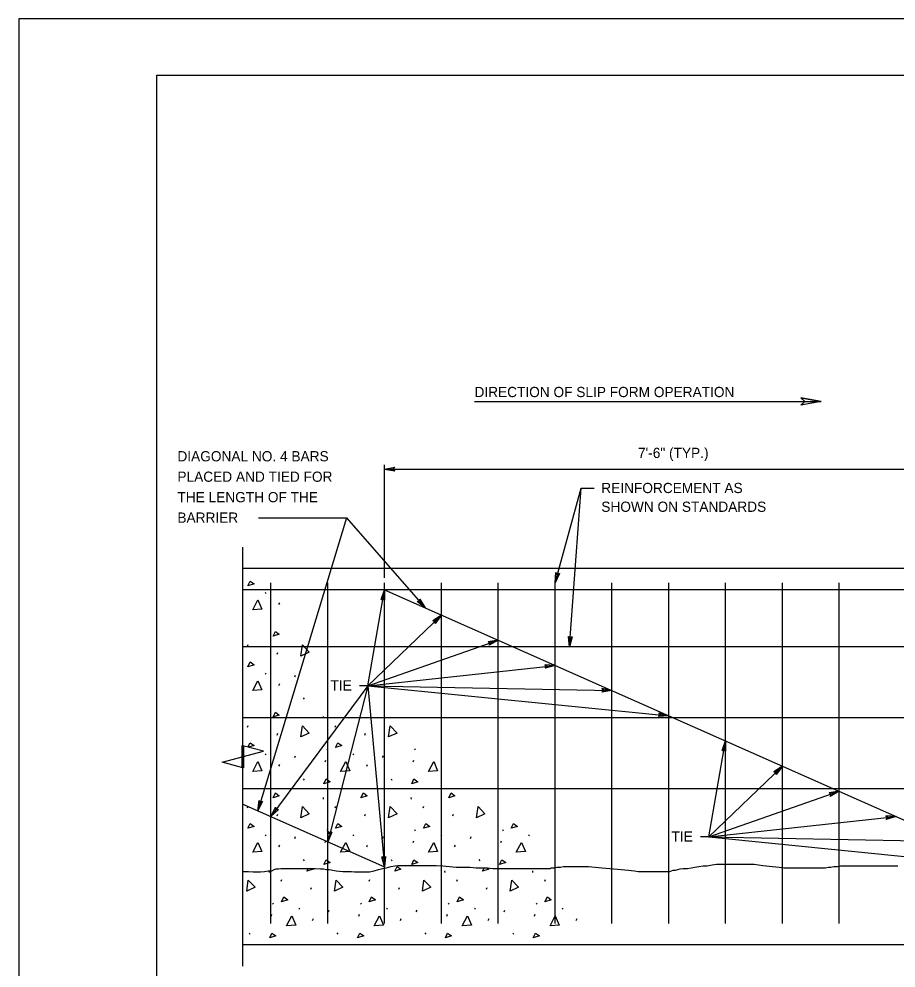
# Model space of a CAD drawing. Extents: x -111.7 to -103.2, y -200 to -189.
# Drawn here: x -111.73 to -106.59, y -194.55 to -188.99 of the extents above; entities that cross this region are included whole.
import ezdxf

# ---------------------------------------------------------------- set-up
doc = ezdxf.new("R2010")
doc.units = 0
for name, color, linetype in [('ANNO-DIMS', 7, 'Continuous'), ('ANNO-TEXT', 7, 'Continuous'), ('BORD-LINE', 7, 'Continuous'), ('DETL-PATT', 7, 'Continuous'), ('Level 10', 7, 'Continuous'), ('Level 12', 7, 'Continuous'), ('SUBS-FOOT_P', 7, 'Continuous'), ('SUPR-PARA_P', 7, 'Continuous'), ('SUPR-RFRC', 7, 'Continuous'), ('USER-CLIP', 7, 'Continuous')]:
    doc.layers.add(name, color=color, linetype=linetype)

msp = doc.modelspace()

# ---------------------------------------------------------------- linework, layer by layer
at = {"layer": 'ANNO-DIMS'}
msp.add_lwpolyline([(-110.4191, -193.3802), (-110.5399, -193.3478), (-110.2984, -193.2831), (-110.4191, -193.2508)], dxfattribs=at)
msp.add_lwpolyline([(-110.4143, -193.3813), (-110.4234, -193.379), (-110.4234, -193.2497), (-110.4143, -193.2521)], close=True, dxfattribs=at)
at = {"layer": 'ANNO-TEXT'}
msp.add_line((-110.4191, -194.5447), (-110.4191, -192.0863), dxfattribs=at)
at = {"layer": 'BORD-LINE'}
msp.add_lwpolyline([(-110.923, -189.3161), (-103.5488, -189.3161), (-103.5488, -199.6692), (-110.923, -199.6692)], close=True, dxfattribs=at)
at = {"layer": 'DETL-PATT'}
for p, q in [((-110.2888, -192.3503), (-110.2837, -192.3568)), ((-110.2077, -192.4225), (-110.2025, -192.4121)), ((-110.3919, -192.6672), (-110.388, -192.6569)), ((-110.218, -192.7136), (-110.2141, -192.7033)), ((-110.2888, -192.8244), (-110.2837, -192.8308)), ((-110.1149, -192.8463), (-110.1098, -192.836)), ((-110.2077, -192.8965), (-110.2025, -192.8862)), ((-110.0647, -192.97), (-110.0595, -192.9777)), ((-109.9487, -193.0795), (-109.9475, -193.0898)), ((-110.3919, -193.1413), (-110.388, -193.131)), ((-110.218, -193.1877), (-110.2141, -193.1774)), ((-109.8766, -193.1413), (-109.8727, -193.131)), ((-109.7027, -193.1877), (-109.6988, -193.1774)), ((-109.9268, -193.2688), (-109.923, -193.2753)), ((-109.4116, -193.2688), (-109.4077, -193.2753)), ((-110.2888, -193.2985), (-110.2837, -193.3049)), ((-110.1149, -193.3204), (-110.1098, -193.31)), ((-109.9359, -193.3448), (-109.932, -193.3345)), ((-109.7735, -193.2985), (-109.7684, -193.3049)), ((-109.5996, -193.3204), (-109.5945, -193.31)), ((-109.4206, -193.3448), (-109.4167, -193.3345)), ((-110.2077, -193.3706), (-110.2025, -193.3603)), ((-109.6924, -193.3706), (-109.6872, -193.3603)), ((-110.0647, -193.444), (-110.0595, -193.4518)), ((-109.5494, -193.444), (-109.5442, -193.4518)), ((-109.9487, -193.5535), (-109.9475, -193.5638)), ((-109.4335, -193.5535), (-109.4322, -193.5638)), ((-110.3919, -193.6154), (-110.388, -193.6051)), ((-109.8766, -193.6154), (-109.8727, -193.6051)), ((-109.3613, -193.6154), (-109.3574, -193.6051)), ((-110.218, -193.6617), (-110.2141, -193.6514)), ((-109.7027, -193.6617), (-109.6988, -193.6514)), ((-109.1874, -193.6617), (-109.1835, -193.6514)), ((-110.2888, -193.7725), (-110.2837, -193.779)), ((-110.1149, -193.7944), (-110.1098, -193.7841)), ((-109.9268, -193.7429), (-109.923, -193.7493)), ((-109.7735, -193.7725), (-109.7684, -193.779)), ((-109.5996, -193.7944), (-109.5945, -193.7841)), ((-109.4116, -193.7429), (-109.4077, -193.7493)), ((-109.2583, -193.7725), (-109.2531, -193.779)), ((-109.0843, -193.7944), (-109.0792, -193.7841)), ((-108.8963, -193.7429), (-108.8924, -193.7493)), ((-108.743, -193.7725), (-108.7378, -193.779)), ((-110.2077, -193.8447), (-110.2025, -193.8344)), ((-109.9359, -193.8189), (-109.932, -193.8086)), ((-109.6924, -193.8447), (-109.6872, -193.8344)), ((-109.4206, -193.8189), (-109.4167, -193.8086)), ((-109.1771, -193.8447), (-109.1719, -193.8344)), ((-108.9053, -193.8189), (-108.9014, -193.8086)), ((-110.0647, -193.9181), (-110.0595, -193.9258)), ((-109.5494, -193.9181), (-109.5442, -193.9258)), ((-109.0341, -193.9181), (-109.0289, -193.9258)), ((-110.2662, -193.9845), (-110.2649, -193.9948)), ((-110.0433, -193.9871), (-110.0349, -193.9701)), ((-109.75, -193.9914), (-109.7496, -193.9948)), ((-109.2356, -193.9845), (-109.2343, -193.9948)), ((-109.0127, -193.9871), (-109.0025, -193.9666)), ((-108.7203, -193.9845), (-108.719, -193.9948)), ((-110.194, -194.0463), (-110.1902, -194.036)), ((-109.6788, -194.0463), (-109.6749, -194.036)), ((-109.1635, -194.0463), (-109.1596, -194.036)), ((-108.6482, -194.0463), (-108.6443, -194.036)), ((-110.0201, -194.0927), (-110.0163, -194.0824)), ((-109.5048, -194.0927), (-109.501, -194.0824)), ((-108.9895, -194.0927), (-108.9857, -194.0824)), ((-110.2443, -194.1739), (-110.2404, -194.1803)), ((-109.729, -194.1739), (-109.7251, -194.1803)), ((-109.2137, -194.1739), (-109.2098, -194.1803)), ((-108.6984, -194.1739), (-108.6945, -194.1803)), ((-110.2533, -194.2499), (-110.2494, -194.2396)), ((-110.091, -194.2035), (-110.0858, -194.2099)), ((-109.9171, -194.2254), (-109.9119, -194.2151)), ((-109.738, -194.2499), (-109.7341, -194.2396)), ((-109.5757, -194.2035), (-109.5705, -194.2099)), ((-109.4018, -194.2254), (-109.3966, -194.2151)), ((-109.2227, -194.2499), (-109.2189, -194.2396)), ((-109.0604, -194.2035), (-109.0552, -194.2099)), ((-108.8865, -194.2254), (-108.8813, -194.2151)), ((-108.7074, -194.2499), (-108.7036, -194.2396)), ((-108.5451, -194.2035), (-108.54, -194.2099)), ((-110.0098, -194.2756), (-110.0047, -194.2653)), ((-109.4945, -194.2756), (-109.4894, -194.2653)), ((-108.9792, -194.2756), (-108.9741, -194.2653)), ((-108.4639, -194.2756), (-108.4588, -194.2653)), ((-110.3821, -194.3491), (-110.377, -194.3568)), ((-109.8668, -194.3491), (-109.8617, -194.3568)), ((-109.3515, -194.3491), (-109.3464, -194.3568)), ((-108.8362, -194.3491), (-108.8311, -194.3568))]:
    msp.add_line(p, q, dxfattribs=at)
for points in [[(-110.3906, -192.313), (-110.3764, -192.2846), (-110.3533, -192.3014), (-110.3906, -192.313)], [(-110.361, -192.4534), (-110.3301, -192.3954), (-110.3069, -192.4495), (-110.361, -192.4534)], [(-110.2412, -192.608), (-110.227, -192.5796), (-110.2051, -192.5964), (-110.2412, -192.608)], [(-110.0789, -192.7252), (-110.0698, -192.6595), (-110.0299, -192.702), (-110.0789, -192.7252)], [(-110.3906, -192.787), (-110.3764, -192.7587), (-110.3533, -192.7754), (-110.3906, -192.787)], [(-110.361, -192.9274), (-110.3301, -192.8695), (-110.3069, -192.9236), (-110.361, -192.9274)], [(-110.2412, -193.082), (-110.227, -193.0537), (-110.2051, -193.0704), (-110.2412, -193.082)], [(-110.0789, -193.1993), (-110.0698, -193.1336), (-110.0299, -193.1761), (-110.0789, -193.1993)], [(-109.5636, -193.1993), (-109.5545, -193.1336), (-109.5146, -193.1761), (-109.5636, -193.1993)], [(-110.3894, -193.2587), (-110.3764, -193.2328), (-110.3533, -193.2495), (-110.386, -193.2597)], [(-109.8753, -193.2611), (-109.8611, -193.2328), (-109.838, -193.2495), (-109.8753, -193.2611)], [(-110.361, -193.4015), (-110.3301, -193.3435), (-110.3069, -193.3976), (-110.361, -193.4015)], [(-109.8457, -193.4015), (-109.8148, -193.3435), (-109.7916, -193.3976), (-109.8457, -193.4015)], [(-109.3304, -193.4015), (-109.2995, -193.3435), (-109.2763, -193.3976), (-109.3304, -193.4015)], [(-109.9436, -193.4737), (-109.9307, -193.4453), (-109.9075, -193.4621), (-109.9436, -193.4737)], [(-109.4283, -193.4737), (-109.4154, -193.4453), (-109.3922, -193.4621), (-109.4283, -193.4737)], [(-110.2412, -193.5561), (-110.227, -193.5278), (-110.2051, -193.5445), (-110.2412, -193.5561)], [(-109.7259, -193.5561), (-109.7117, -193.5278), (-109.6898, -193.5445), (-109.7259, -193.5561)], [(-109.2106, -193.5561), (-109.1964, -193.5278), (-109.1745, -193.5445), (-109.2106, -193.5561)], [(-110.0789, -193.6733), (-110.0698, -193.6076), (-110.0299, -193.6501), (-110.0789, -193.6733)], [(-109.5636, -193.6733), (-109.5545, -193.6076), (-109.5146, -193.6501), (-109.5636, -193.6733)], [(-109.0483, -193.6733), (-109.0393, -193.6076), (-108.9993, -193.6501), (-109.0483, -193.6733)], [(-110.3906, -193.7352), (-110.3764, -193.7068), (-110.3533, -193.7236), (-110.3906, -193.7352)], [(-109.8753, -193.7352), (-109.8611, -193.7068), (-109.838, -193.7236), (-109.8753, -193.7352)], [(-109.36, -193.7352), (-109.3459, -193.7068), (-109.3227, -193.7236), (-109.36, -193.7352)], [(-108.8447, -193.7352), (-108.8306, -193.7068), (-108.8074, -193.7236), (-108.8447, -193.7352)], [(-110.361, -193.8756), (-110.3301, -193.8176), (-110.3069, -193.8717), (-110.361, -193.8756)], [(-109.8457, -193.8756), (-109.8148, -193.8176), (-109.7916, -193.8717), (-109.8457, -193.8756)], [(-109.3304, -193.8756), (-109.2995, -193.8176), (-109.2763, -193.8717), (-109.3304, -193.8756)], [(-108.8151, -193.8756), (-108.7842, -193.8176), (-108.761, -193.8717), (-108.8151, -193.8756)], [(-109.9436, -193.9477), (-109.9307, -193.9194), (-109.9075, -193.9361), (-109.9436, -193.9477)], [(-109.528, -193.9871), (-109.5139, -193.9587), (-109.492, -193.9755), (-109.528, -193.9871)], [(-109.4283, -193.9477), (-109.4154, -193.9194), (-109.3922, -193.9361), (-109.4283, -193.9477)], [(-108.913, -193.9477), (-108.9001, -193.9194), (-108.8769, -193.9361), (-108.913, -193.9477)], [(-110.0142, -193.9701), (-110.0073, -193.9755), (-110.0433, -193.9871)], [(-108.9883, -193.9666), (-108.9767, -193.9755), (-109.0127, -193.9871)], [(-110.3963, -194.1043), (-110.3873, -194.0386), (-110.3473, -194.0811), (-110.3963, -194.1043)], [(-109.881, -194.1043), (-109.872, -194.0386), (-109.8321, -194.0811), (-109.881, -194.1043)], [(-109.3657, -194.1043), (-109.3567, -194.0386), (-109.3168, -194.0811), (-109.3657, -194.1043)], [(-108.8504, -194.1043), (-108.8414, -194.0386), (-108.8015, -194.0811), (-108.8504, -194.1043)], [(-110.1928, -194.1661), (-110.1786, -194.1378), (-110.1554, -194.1545), (-110.1928, -194.1661)], [(-109.6775, -194.1661), (-109.6633, -194.1378), (-109.6401, -194.1545), (-109.6775, -194.1661)], [(-109.1622, -194.1661), (-109.148, -194.1378), (-109.1248, -194.1545), (-109.1622, -194.1661)], [(-108.6469, -194.1661), (-108.6327, -194.1378), (-108.6095, -194.1545), (-108.6469, -194.1661)], [(-110.1631, -194.3065), (-110.1322, -194.2486), (-110.109, -194.3027), (-110.1631, -194.3065)], [(-109.6478, -194.3065), (-109.6169, -194.2486), (-109.5937, -194.3027), (-109.6478, -194.3065)], [(-109.1325, -194.3065), (-109.1016, -194.2486), (-109.0784, -194.3027), (-109.1325, -194.3065)], [(-108.6172, -194.3065), (-108.5863, -194.2486), (-108.5631, -194.3027), (-108.6172, -194.3065)], [(-110.261, -194.3787), (-110.2482, -194.3503), (-110.225, -194.3671), (-110.261, -194.3787)], [(-109.7457, -194.3787), (-109.7329, -194.3503), (-109.7097, -194.3671), (-109.7457, -194.3787)], [(-109.2304, -194.3787), (-109.2176, -194.3503), (-109.1944, -194.3671), (-109.2304, -194.3787)], [(-108.7152, -194.3787), (-108.7023, -194.3503), (-108.6791, -194.3671), (-108.7152, -194.3787)]]:
    msp.add_lwpolyline(points, dxfattribs=at)
at = {"layer": 'Level 10'}
for p, q in [((-109.0603, -191.2304), (-107.0263, -191.2304)), ((-107.0263, -191.2304), (-107.1456, -191.2094)), ((-107.1456, -191.2094), (-107.1229, -191.2304)), ((-107.0263, -191.2304), (-107.1456, -191.2514)), ((-107.1229, -191.2304), (-107.1456, -191.2514)), ((-109.5877, -192.2652), (-109.5877, -191.602)), ((-109.5877, -191.627), (-109.5282, -191.6165)), ((-109.5394, -191.627), (-109.5282, -191.6165)), ((-109.5877, -191.627), (-105.9211, -191.627)), ((-109.5877, -191.627), (-109.5282, -191.6375)), ((-109.5282, -191.6375), (-109.5394, -191.627)), ((-108.5877, -192.2947), (-108.435, -191.7383)), ((-108.5029, -192.6697), (-108.435, -191.7383)), ((-108.435, -191.7383), (-108.3581, -191.7383)), ((-109.8116, -191.9126), (-110.3311, -193.6319)), ((-110.3261, -191.9126), (-109.8116, -191.9126)), ((-109.8116, -191.9126), (-109.3501, -192.4416)), ((-108.5877, -192.2947), (-108.5822, -192.2344)), ((-108.5749, -192.248), (-108.5822, -192.2344)), ((-108.5877, -192.2947), (-108.5619, -192.2401)), ((-108.5619, -192.2401), (-108.5749, -192.248)), ((-109.6859, -192.8994), (-109.5877, -192.3363)), ((-109.5877, -192.3363), (-109.6082, -192.3932)), ((-109.5877, -192.3363), (-109.5876, -192.3967)), ((-109.6082, -192.3932), (-109.596, -192.3839)), ((-109.596, -192.3839), (-109.5876, -192.3967)), ((-109.3501, -192.4416), (-109.3971, -192.4035)), ((-109.3818, -192.4053), (-109.3971, -192.4035)), ((-109.3812, -192.3899), (-109.3818, -192.4053)), ((-109.3501, -192.4416), (-109.3812, -192.3899)), ((-109.6859, -192.8994), (-109.2544, -192.4841)), ((-109.2544, -192.4841), (-109.3045, -192.5178)), ((-109.2544, -192.4841), (-109.2899, -192.5329)), ((-109.3045, -192.5178), (-109.2892, -192.5175)), ((-109.2892, -192.5175), (-109.2899, -192.5329)), ((-108.5029, -192.6697), (-108.5092, -192.6094)), ((-108.4993, -192.6214), (-108.5092, -192.6094)), ((-108.5029, -192.6697), (-108.4881, -192.6109)), ((-108.4881, -192.6109), (-108.4993, -192.6214)), ((-109.6859, -192.8994), (-108.921, -192.6318)), ((-108.921, -192.6318), (-108.9807, -192.6416)), ((-108.9807, -192.6416), (-108.9666, -192.6477)), ((-108.921, -192.6318), (-108.9737, -192.6614)), ((-108.9666, -192.6477), (-108.9737, -192.6614)), ((-109.6859, -192.8994), (-108.5877, -192.7795)), ((-108.5877, -192.7795), (-108.648, -192.7756)), ((-108.648, -192.7756), (-108.6357, -192.7847)), ((-108.5877, -192.7795), (-108.6457, -192.7964)), ((-108.6357, -192.7847), (-108.6457, -192.7964)), ((-109.6859, -192.8994), (-110.2544, -193.6659)), ((-109.6859, -192.8994), (-109.921, -193.8136)), ((-109.6859, -192.8994), (-109.7343, -192.8994)), ((-109.6859, -192.8994), (-108.2544, -192.9272)), ((-109.6859, -192.8994), (-107.921, -193.075)), ((-109.6859, -192.8994), (-109.5877, -193.9613)), ((-108.3027, -192.9263), (-108.3141, -192.9366)), ((-108.2544, -192.9272), (-108.3141, -192.9366)), ((-108.2544, -192.9272), (-108.3137, -192.9157)), ((-108.3137, -192.9157), (-108.3027, -192.9263)), ((-107.9691, -193.0702), (-107.9813, -193.0796)), ((-107.921, -193.075), (-107.9792, -193.0587)), ((-107.9792, -193.0587), (-107.9691, -193.0702)), ((-107.921, -193.075), (-107.9813, -193.0796)), ((-107.6859, -193.7857), (-107.5877, -193.2227)), ((-107.5877, -193.2227), (-107.6082, -193.2795)), ((-107.5877, -193.2227), (-107.5876, -193.2831)), ((-107.6082, -193.2795), (-107.596, -193.2703)), ((-107.596, -193.2703), (-107.5876, -193.2831)), ((-107.6859, -193.7857), (-107.2544, -193.3704)), ((-107.2544, -193.3704), (-107.3045, -193.4042)), ((-107.3045, -193.4042), (-107.2892, -193.4039)), ((-107.2544, -193.3704), (-107.2899, -193.4193)), ((-107.2892, -193.4039), (-107.2899, -193.4193)), ((-110.3311, -193.6319), (-110.324, -193.5719)), ((-110.3172, -193.5856), (-110.324, -193.5719)), ((-107.6859, -193.7857), (-106.9211, -193.5181)), ((-106.9211, -193.5181), (-106.9807, -193.528)), ((-106.9807, -193.528), (-106.9666, -193.5341)), ((-106.9211, -193.5181), (-106.9737, -193.5477)), ((-106.9666, -193.5341), (-106.9737, -193.5477)), ((-110.3311, -193.6319), (-110.3039, -193.5779)), ((-110.3039, -193.5779), (-110.3172, -193.5856)), ((-110.2544, -193.6659), (-110.2274, -193.6118)), ((-110.2544, -193.6659), (-110.2105, -193.6243)), ((-110.2256, -193.6271), (-110.2274, -193.6118)), ((-110.2105, -193.6243), (-110.2256, -193.6271)), ((-107.6859, -193.7857), (-106.5877, -193.6659)), ((-106.5877, -193.6659), (-106.648, -193.662)), ((-106.648, -193.662), (-106.6357, -193.6711)), ((-106.5877, -193.6659), (-106.6457, -193.6828)), ((-106.6357, -193.6711), (-106.6457, -193.6828)), ((-109.921, -193.8136), (-109.9164, -193.7534)), ((-109.921, -193.8136), (-109.8961, -193.7586)), ((-109.909, -193.7668), (-109.9164, -193.7534)), ((-109.8961, -193.7586), (-109.909, -193.7668)), ((-107.6859, -193.7857), (-107.7343, -193.7857)), ((-107.6859, -193.7857), (-106.2544, -193.8136)), ((-107.6859, -193.7857), (-105.9211, -193.9613)), ((-109.5877, -193.9613), (-109.6037, -193.9031)), ((-109.5922, -193.9133), (-109.6037, -193.9031)), ((-109.5828, -193.9011), (-109.5922, -193.9133)), ((-109.5877, -193.9613), (-109.5828, -193.9011))]:
    msp.add_line(p, q, dxfattribs=at)
for points in [[(-107.1456, -191.2094), (-107.0263, -191.2304), (-107.1456, -191.2514), (-107.1229, -191.2304)], [(-109.5282, -191.6375), (-109.5877, -191.627), (-109.5282, -191.6165), (-109.5394, -191.627)], [(-108.5619, -192.2401), (-108.5877, -192.2947), (-108.5822, -192.2344), (-108.5749, -192.248)], [(-109.6082, -192.3932), (-109.5877, -192.3363), (-109.5876, -192.3967), (-109.596, -192.3839)], [(-109.3812, -192.3899), (-109.3501, -192.4416), (-109.3971, -192.4035), (-109.3818, -192.4053)], [(-109.3045, -192.5178), (-109.2544, -192.4841), (-109.2899, -192.5329), (-109.2892, -192.5175)], [(-108.4881, -192.6109), (-108.5029, -192.6697), (-108.5092, -192.6094), (-108.4993, -192.6214)], [(-108.9807, -192.6416), (-108.921, -192.6318), (-108.9737, -192.6614), (-108.9666, -192.6477)], [(-108.648, -192.7756), (-108.5877, -192.7795), (-108.6457, -192.7964), (-108.6357, -192.7847)], [(-108.3137, -192.9157), (-108.2544, -192.9272), (-108.3141, -192.9366), (-108.3027, -192.9263)], [(-107.9792, -193.0587), (-107.921, -193.075), (-107.9813, -193.0796), (-107.9691, -193.0702)], [(-107.6082, -193.2795), (-107.5877, -193.2227), (-107.5876, -193.2831), (-107.596, -193.2703)], [(-107.3045, -193.4042), (-107.2544, -193.3704), (-107.2899, -193.4193), (-107.2892, -193.4039)], [(-110.3039, -193.5779), (-110.3311, -193.6319), (-110.324, -193.5719), (-110.3172, -193.5856)], [(-106.9807, -193.528), (-106.9211, -193.5181), (-106.9737, -193.5477), (-106.9666, -193.5341)], [(-110.2105, -193.6243), (-110.2544, -193.6659), (-110.2274, -193.6118), (-110.2256, -193.6271)], [(-106.648, -193.662), (-106.5877, -193.6659), (-106.6457, -193.6828), (-106.6357, -193.6711)], [(-109.8961, -193.7586), (-109.921, -193.8136), (-109.9164, -193.7534), (-109.909, -193.7668)], [(-109.5828, -193.9011), (-109.5877, -193.9613), (-109.6037, -193.9031), (-109.5922, -193.9133)]]:
    msp.add_lwpolyline(points, close=True, dxfattribs=at)
at = {"layer": 'SUBS-FOOT_P'}
msp.add_line((-105.8377, -194.4197), (-110.4191, -194.4197), dxfattribs=at)
msp.add_lwpolyline([(-110.4191, -193.9878), (-110.4149, -193.9878), (-110.3866, -193.9878), (-110.3584, -193.9914), (-110.316, -193.9914), (-110.2913, -193.9878), (-110.2701, -193.9843), (-110.2489, -193.9843), (-110.2347, -193.9772), (-110.2241, -193.9737), (-110.21, -193.9737), (-110.1959, -193.9701), (-110.1782, -193.9701), (-110.1605, -193.9701), (-110.1393, -193.9701), (-110.1252, -193.9701), (-110.0934, -193.9701), (-110.0722, -193.9701), (-110.051, -193.9701), (-110.0192, -193.9701), (-109.9945, -193.9701), (-109.9627, -193.9737), (-109.945, -193.9737), (-109.9273, -193.9772), (-109.9097, -193.9772), (-109.892, -193.9807), (-109.8708, -193.9843), (-109.832, -193.9878), (-109.8072, -193.9878), (-109.7825, -193.9878), (-109.7648, -193.9914), (-109.7472, -193.9914), (-109.7295, -193.9914), (-109.7118, -193.9914), (-109.6942, -193.9914), (-109.6765, -193.9914), (-109.6482, -193.9843), (-109.6235, -193.9772), (-109.5988, -193.9701), (-109.5776, -193.9666), (-109.5493, -193.9595), (-109.5281, -193.956), (-109.5104, -193.9525), (-109.4928, -193.9525), (-109.4645, -193.9525), (-109.4398, -193.9525), (-109.4045, -193.9525), (-109.3762, -193.9525), (-109.3515, -193.9525), (-109.3267, -193.9525), (-109.3055, -193.9525), (-109.2843, -193.9525), (-109.2455, -193.956), (-109.2066, -193.9595), (-109.1677, -193.9631), (-109.1253, -193.9631), (-109.0865, -193.9631), (-109.0512, -193.9666), (-109.0194, -193.9666), (-108.984, -193.9666), (-108.9522, -193.9701), (-108.9134, -193.9701), (-108.8745, -193.9701), (-108.825, -193.9701), (-108.7614, -193.9701), (-108.7084, -193.9701), (-108.6696, -193.9701), (-108.6484, -193.9701), (-108.6272, -193.9701), (-108.6166, -193.9701), (-108.6095, -193.9666), (-108.6025, -193.9666), (-108.5919, -193.9666), (-108.5777, -193.9631), (-108.5565, -193.9631), (-108.5389, -193.9595), (-108.5177, -193.9595), (-108.5, -193.9595), (-108.4859, -193.9595), (-108.4682, -193.9595), (-108.4541, -193.9595), (-108.4364, -193.9595), (-108.4152, -193.9595), (-108.3905, -193.9595), (-108.3516, -193.9631), (-108.3127, -193.9666), (-108.2668, -193.9701), (-108.1997, -193.9772), (-108.1573, -193.9807), (-108.122, -193.9843), (-108.1008, -193.9878), (-108.0866, -193.9878), (-108.0725, -193.9878), (-108.0584, -193.9878), (-108.0478, -193.9878), (-108.0266, -193.9878), (-108.0054, -193.9878), (-107.9806, -193.9878), (-107.9418, -193.9878), (-107.9135, -193.9878), (-107.8958, -193.9807), (-107.8817, -193.9807), (-107.8676, -193.9772), (-107.8534, -193.9737), (-107.8358, -193.9701), (-107.8111, -193.9701), (-107.7899, -193.9666), (-107.7687, -193.9631), (-107.7439, -193.9595), (-107.7192, -193.956), (-107.6945, -193.956), (-107.6662, -193.9489), (-107.6415, -193.9454), (-107.6203, -193.9454), (-107.6026, -193.9454), (-107.5814, -193.9454), (-107.5637, -193.9454), (-107.5461, -193.9454), (-107.5249, -193.9454), (-107.4966, -193.9454), (-107.4613, -193.9454), (-107.4189, -193.9454), (-107.3694, -193.9525), (-107.3129, -193.9595), (-107.274, -193.9631), (-107.2458, -193.9666), (-107.2316, -193.9666), (-107.221, -193.9666), (-107.2104, -193.9666), (-107.2034, -193.9666), (-107.1963, -193.9666), (-107.1857, -193.9666), (-107.168, -193.9666), (-107.1504, -193.9666), (-107.1115, -193.9666), (-107.0868, -193.9666), (-107.0691, -193.9666), (-107.0585, -193.9666), (-107.0444, -193.9666), (-107.0232, -193.9666), (-107.002, -193.9666), (-106.9843, -193.9631), (-106.9702, -193.9631), (-106.9525, -193.9595), (-106.9313, -193.9595), (-106.9137, -193.956), (-106.8854, -193.956), (-106.8748, -193.956), (-106.8571, -193.956), (-106.8324, -193.956), (-106.8077, -193.956), (-106.7723, -193.956), (-106.7476, -193.956), (-106.7193, -193.956), (-106.6805, -193.956), (-106.6557, -193.956), (-106.6345, -193.956), (-106.6239, -193.956), (-106.6098, -193.956), (-106.6027, -193.956), (-106.5886, -193.956), (-106.578, -193.956)], dxfattribs=at)
at = {"layer": 'SUPR-PARA_P'}
msp.add_line((-105.8377, -192.2113), (-110.4191, -192.2113), dxfattribs=at)
at = {"layer": 'SUPR-RFRC'}
for p, q in [((-105.9211, -192.3363), (-110.4191, -192.3363)), ((-110.2544, -194.2947), (-110.2544, -192.2947)), ((-109.921, -194.2947), (-109.921, -192.2947)), ((-109.5877, -194.2947), (-109.5877, -192.2947)), ((-109.5877, -192.3363), (-105.9211, -193.9613)), ((-109.2544, -194.2947), (-109.2544, -192.2947)), ((-108.921, -194.2947), (-108.921, -192.2947)), ((-108.5877, -194.2947), (-108.5877, -192.2947)), ((-108.2544, -194.2947), (-108.2544, -192.2947)), ((-107.921, -194.2947), (-107.921, -192.2947)), ((-107.5877, -194.2947), (-107.5877, -192.2947)), ((-107.2544, -194.2947), (-107.2544, -192.2947)), ((-106.9211, -194.2947), (-106.9211, -192.2947)), ((-105.9211, -192.6697), (-110.4191, -192.6697)), ((-105.9211, -193.0863), (-110.4191, -193.0863)), ((-105.9211, -193.503), (-110.4191, -193.503)), ((-110.4191, -193.5929), (-109.5877, -193.9613))]:
    msp.add_line(p, q, dxfattribs=at)
at = {"layer": 'USER-CLIP'}
msp.add_lwpolyline([(-103.2319, -188.9861), (-111.7319, -188.9861), (-111.7319, -199.9861), (-103.2319, -199.9861)], close=True, dxfattribs=at)

# ---------------------------------------------------------------- texts
at = {"layer": 'Level 12'}
for s, p in [('DIRECTION OF SLIP FORM OPERATION', (-109.0603, -191.205)), ('7\'-6" (TYP.)', (-108.1011, -191.5622)), ('DIAGONAL NO. 4 BARS', (-110.8027, -191.582)), ('PLACED AND TIED FOR', (-110.8027, -191.702)), ('REINFORCEMENT AS', (-108.3164, -191.7682)), ('THE LENGTH OF THE', (-110.8027, -191.822)), ('SHOWN ON STANDARDS', (-108.3164, -191.8782)), ('BARRIER', (-110.8027, -191.942)), ('TIE', (-109.9046, -192.9269)), ('TIE', (-107.9046, -193.8132))]:
    msp.add_text(s, height=0.06, dxfattribs=at).set_placement(p)

doc.saveas('drawing.dxf')
